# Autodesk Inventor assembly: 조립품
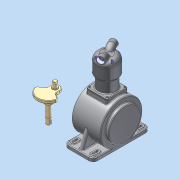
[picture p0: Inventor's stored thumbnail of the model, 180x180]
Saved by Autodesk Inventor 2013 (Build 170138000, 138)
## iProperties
Created: 2015-06
Part Number: 조립품
Document SubType Name: Assembly
Designer: Administrator
Author: Administrator
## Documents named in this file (6)
- C:\Users\Administrator\Desktop\450606V1012\조립품.iam
- C:\Users\Administrator\Desktop\450606V1012\본체.ipt
- C:\Users\Administrator\Desktop\450606V1012\실린더.ipt
- C:\Users\Administrator\Desktop\450606V1012\실린더헤드.ipt
- C:\Users\Administrator\Desktop\450606V1012\메인커버.ipt
- C:\Users\Administrator\Desktop\450606V1012\메인 크랭크 축-구동부.ipt
